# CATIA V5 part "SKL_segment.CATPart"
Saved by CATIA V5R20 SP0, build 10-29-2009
Part number: SKL_segment
Publications: "Plan_Ref", "D", "E", "Segment_ED", "Axe_D_segment", "Axe_E_segment", "Plan_Ter", "Plan_Sec"
Bounding box of the stored display mesh (mm): x -5 to 5, y 0 to 9.366, z 0 to 5.79
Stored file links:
  C:\Users\MATT\Desktop\CATIA_Projet_IAO\CATIA FINAL\SKL_segment.CATPart
  C:\Users\MATT\Desktop\CATIA_Projet_IAO\CATIA FINAL\SKL_Parametre_Projet_IAO.CATProduct
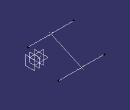
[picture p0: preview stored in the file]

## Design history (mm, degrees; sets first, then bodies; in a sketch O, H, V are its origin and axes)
External parameters (linked from other documents)
  External.AC = 3 mm
  `External.Paramètre2` = 2.46 mm
  External.CoeffAC = 3
Set1
  Plane1 "Plan_Ref": type Offset, RefPlane Plane4, Offset 0
  Point1 "D": (0, 0, 0), relative to Point3
  Sketch1 on Plane1, origin (0, 0, 0), H (0, 1, 0), V (0, 0, 1)
    circle A1 centre (9.3656, 2.7702) radius 7.38
    point P1 (9.3656, 2.7702)
    circle A2 centre (0, 0) radius 6.36
    point P2 (0, 0)
    reference projected point E1 (0, 0) from Point4
    reference projected point E2 (9.3656, 2.7702) from Point1
    point P3 (2.6317, 5.79)
    radius A2 = 6.36 {= 2.12*External.AC}
    radius A1 = 7.38 {= `External.Paramètre2` *External.CoeffAC}
    coincidence: P2 E1, P1 E2, P3 A1, P3 A2
  Point2 "E": (0, 0, 0), relative to Sketch1.P3
  Line1 "Segment_ED": type PtPt, FirstPoint Point1, SecondPoint Point2
  Line2 "Axe_D_segment": type Normal, RefPoint Point1, RefSkin Plane1, Start -5, End 5
  Line3 "Axe_E_segment": type Normal, RefPoint Point2, RefSkin Plane1, Start -5, End 5
  Plane2 "Plan_Sec": type Offset, RefPlane Plane5, Offset 0
  Plane3 "Plan_Ter": type Offset, RefPlane Plane6, Offset 0
Set2
  Plane4 "Plan_Ref": linked copy from another document
  Point3 "D": linked copy from another document
  Point4 "G": linked copy from another document
  Plane5 "Plan_Sec": linked copy from another document
  Plane6 "Plan_Ter": linked copy from another document
Body1 (main body)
